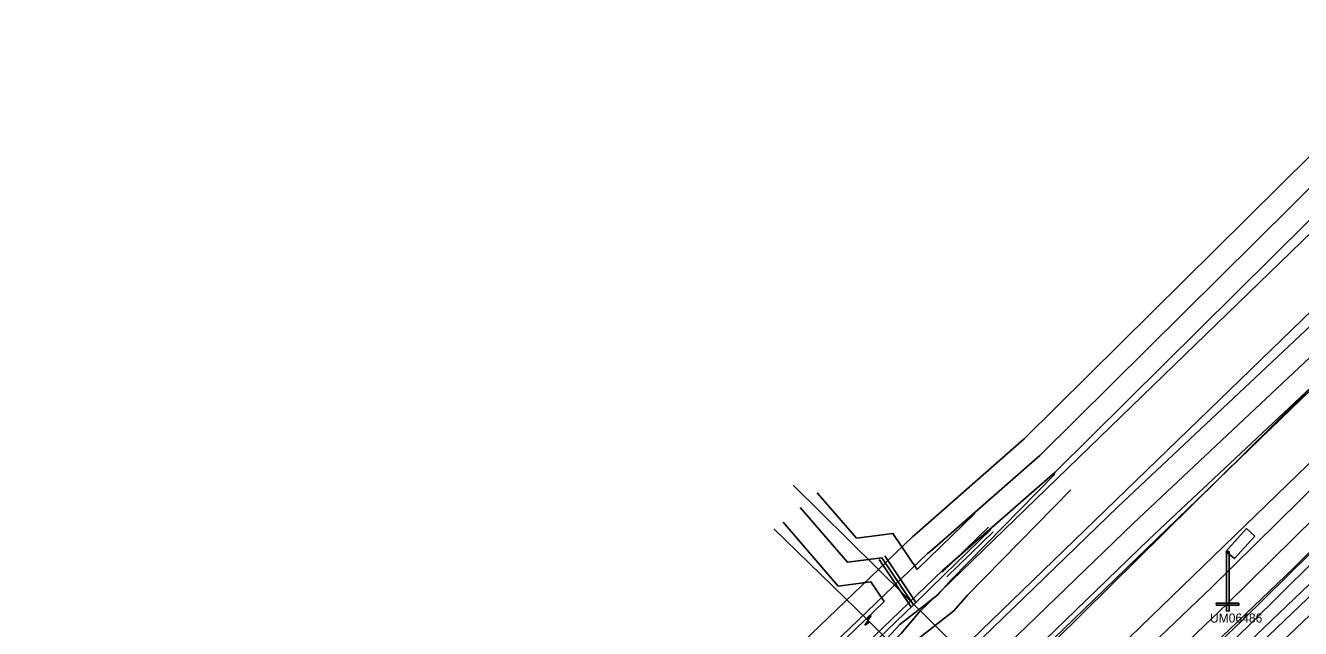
# Model space of a CAD drawing. Extents: x -762993 to -761845, y -975230 to -974501.
# Drawn here: x -762261.1 to -762204.7, y -974943.8 to -974917.1 of the extents above; entities that cross this region are included whole.
import ezdxf

# ---------------------------------------------------------------- set-up
doc = ezdxf.new("R2010")
doc.units = 0
for name, color, linetype in [('IS_CETIN_chranicka', 7, 'Continuous'), ('IS_CETIN_OP', 7, 'Continuous'), ('IS_CETIN_podzem metalika zam', 7, 'Continuous'), ('IS_CETIN_podzem optika zam', 7, 'Continuous'), ('IS_CEZ-D_el vedeni NN podzem', 7, 'Continuous'), ('IS_CEZ-D_el vedeni VN podzem', 7, 'Continuous'), ('IS_CEZ-D_el vedeni VN podzem soubeh investice', 7, 'Continuous'), ('IS_CEZ-D_OP', 7, 'Continuous'), ('IS_CEZ-T_parovod', 7, 'Continuous'), ('IS_CEZ-T_parovod OP', 7, 'Continuous'), ('IS_DPmUL_OP', 7, 'Continuous'), ('IS_DPmUL_VO lampy', 7, 'Continuous'), ('IS_DPmUL_VO lampy anotace', 7, 'Continuous'), ('IS_DPmUL_VO vedeni podzem', 7, 'Continuous'), ('IS_GASNET_plyn NTL rad', 7, 'Continuous'), ('IS_GASNET_plyn OP', 7, 'Continuous'), ('IS_SCVK_kanalizace jednotna', 7, 'Continuous'), ('IS_SCVK_vodovod pripojky', 7, 'Continuous'), ('IS_SCVK_vodovod privadec', 7, 'Continuous'), ('IS_SCVK_vodovod znaky', 7, 'Continuous'), ('IS_TPS_podzem metalika', 7, 'Continuous')]:
    doc.layers.add(name, color=color, linetype=linetype)

msp = doc.modelspace()

# ---------------------------------------------------------------- linework, layer by layer
at = {"layer": 'IS_CETIN_chranicka'}
for points in [[(-762218.494, -974939.302), (-762220.544, -974941.292)], [(-762218.286, -974939.518), (-762220.336, -974941.508)], [(-762223.334, -974940.744), (-762221.934, -974942.824)], [(-762223.086, -974940.576), (-762221.686, -974942.656)]]:
    msp.add_lwpolyline(points, dxfattribs=at)
at = {"layer": 'IS_CETIN_OP'}
for points in [[(-762221.651, -974941.186), (-762222.726, -974939.588), (-762224.334, -974939.798), (-762226.072, -974937.778)], [(-762214.836, -974937.65), (-762219.414, -974942.321), (-762220.029, -974943.012)], [(-762223.108, -974942.602), (-762223.694, -974941.732), (-762225.146, -974941.922), (-762227.588, -974939.082)], [(-762221.651, -974941.186), (-762221.138, -974940.684), (-762219.087, -974938.692)], [(-762240.314, -974959.621), (-762235.368, -974954.443), (-762229.198, -974948.525), (-762226.125, -974945.639), (-762225.209, -974944.624), (-762223.108, -974942.602)], [(-762220.029, -974943.012), (-762221.734, -974944.362), (-762224.313, -974947.13)]]:
    msp.add_lwpolyline(points, dxfattribs=at)
at = {"layer": 'IS_CETIN_podzem metalika zam'}
for points in [[(-762215.55, -974936.95), (-762220.145, -974941.638), (-762220.718, -974942.282)], [(-762221.81, -974942.74), (-762223.21, -974940.66), (-762224.74, -974940.86), (-762226.83, -974938.43)], [(-762220.718, -974942.282), (-762222.414, -974943.625), (-762225.045, -974946.448)]]:
    msp.add_lwpolyline(points, dxfattribs=at)
at = {"layer": 'IS_CETIN_podzem optika zam'}
for points in [[(-762221.81, -974942.74), (-762220.44, -974941.4), (-762218.39, -974939.41)], [(-762240.2, -974960.95), (-762234.66, -974955.15), (-762228.51, -974949.25), (-762225.41, -974946.34), (-762224.49, -974945.32), (-762221.81, -974942.74)]]:
    msp.add_lwpolyline(points, dxfattribs=at)
at = {"layer": 'IS_CEZ-D_el vedeni NN podzem'}
msp.add_lwpolyline([(-762247.847, -974984.536), (-762246.114, -974982.893), (-762246.05, -974980.697), (-762253.7, -974972.107), (-762252.057, -974970.493), (-762250.973, -974969.428), (-762239.791, -974958.41), (-762235.916, -974954.845), (-762234.541, -974953.31), (-762221.186, -974940.477), (-762220.991, -974940.306), (-762216.22, -974936.128), (-762203.456, -974923.483), (-762203.186, -974923.213), (-762202.673, -974922.708), (-762197.126, -974917.211), (-762182.367, -974902.622)], dxfattribs=at)
at = {"layer": 'IS_CEZ-D_el vedeni VN podzem'}
msp.add_lwpolyline([(-762178.94, -974917.38), (-762180.88, -974919.33), (-762183.85, -974922.18), (-762189.02, -974927.27), (-762191.6, -974929.28), (-762204.29, -974941.85), (-762215.61, -974952.68), (-762222.04, -974959.06), (-762225.71, -974962.96), (-762226.91, -974964.67), (-762236.89, -974974.42), (-762240.73, -974978.21), (-762245.09, -974982.81)], dxfattribs=at)
at = {"layer": 'IS_CEZ-D_el vedeni VN podzem soubeh investice'}
msp.add_lwpolyline([(-762246.655, -974985.018), (-762244.801, -974983.086), (-762240.444, -974978.49), (-762236.61, -974974.705), (-762226.604, -974964.93), (-762225.399, -974963.213), (-762221.753, -974959.339), (-762215.331, -974952.967), (-762204.011, -974942.137), (-762191.335, -974929.581), (-762188.756, -974927.571), (-762183.571, -974922.467), (-762180.6, -974919.615), (-762178.658, -974917.664), (-762169.2, -974908.366)], dxfattribs=at)
at = {"layer": 'IS_CEZ-D_OP'}
for points in [[(-762235.261, -974952.615), (-762221.862, -974939.74), (-762221.65, -974939.554), (-762216.902, -974935.396), (-762204.161, -974922.774), (-762203.89, -974922.503), (-762203.376, -974921.997), (-762197.829, -974916.5), (-762183.107, -974901.948), (-762182.738, -974901.004), (-762180.901, -974896.322), (-762175.443, -974882.405), (-762170.837, -974870.904), (-762171.08, -974867.387), (-762172.169, -974851.621), (-762173.361, -974831.196), (-762173.4, -974830.555), (-762173.438, -974829.89), (-762173.725, -974824.972), (-762174.311, -974821.59), (-762174.662, -974815.176), (-762174.624, -974813.433), (-762174.492, -974807.288)], [(-762252.034, -974971.872), (-762251.356, -974971.206), (-762250.272, -974970.141), (-762239.101, -974959.134), (-762235.203, -974955.548), (-762233.821, -974954.005), (-762220.51, -974941.214), (-762220.332, -974941.058), (-762215.538, -974936.86), (-762202.751, -974924.192), (-762202.482, -974923.923), (-762201.97, -974923.419), (-762196.423, -974917.922), (-762181.665, -974903.334)], [(-762179.649, -974916.675), (-762181.581, -974918.616), (-762184.547, -974921.463), (-762189.68, -974926.517), (-762192.261, -974928.528), (-762204.988, -974941.133), (-762212.335, -974948.163)], [(-762178.231, -974918.085), (-762180.179, -974920.044), (-762183.153, -974922.897), (-762188.36, -974928.023), (-762190.939, -974930.032), (-762203.592, -974942.567), (-762210.996, -974949.649)]]:
    msp.add_lwpolyline(points, dxfattribs=at)
at = {"layer": 'IS_CEZ-T_parovod'}
msp.add_line((-762219.73, -974944.77), (-762227.14, -974937.44), dxfattribs=at)
msp.add_lwpolyline([(-762252.5, -975008.59), (-762252.58, -975007.19), (-762253.19, -974987.18), (-762253.2, -974985.67), (-762257.54, -974981.54), (-762246.7, -974971.01), (-762237.24, -974961.81), (-762238.76, -974960.21), (-762237.06, -974958.42), (-762235.35, -974960.05), (-762220.52, -974945.72), (-762219.73, -974944.77), (-762200.92, -974926.55), (-762198.18, -974929.41), (-762193.38, -974924.68)], dxfattribs=at)
at = {"layer": 'IS_CEZ-T_parovod OP'}
for points in [[(-762254.996, -975008.733), (-762255.078, -975007.299), (-762255.69, -974987.226), (-762255.693, -974986.749), (-762261.147, -974981.559), (-762248.442, -974969.217), (-762240.754, -974961.74), (-762242.208, -974960.21), (-762237.148, -974954.882), (-762235.362, -974956.585), (-762222.355, -974944.017), (-762221.566, -974943.068), (-762200.854, -974923.005), (-762198.129, -974925.85), (-762195.116, -974922.881)], [(-762250.004, -975008.447), (-762250.082, -975007.081), (-762250.69, -974987.134), (-762250.707, -974984.591), (-762253.933, -974981.521), (-762244.958, -974972.803), (-762235.373, -974963.482), (-762235.338, -974963.515), (-762218.685, -974947.423), (-762217.894, -974946.472), (-762200.986, -974930.095), (-762198.231, -974932.97), (-762193.371, -974928.181)]]:
    msp.add_lwpolyline(points, dxfattribs=at)
at = {"layer": 'IS_DPmUL_OP'}
for p, q in [((-762228.861, -974961.348), (-762208.613, -974941.975)), ((-762227.465, -974962.78), (-762207.231, -974943.421))]:
    msp.add_line(p, q, dxfattribs=at)
for points in [[(-762208.624, -974941.986), (-762192.88, -974926.476)], [(-762207.22, -974943.41), (-762191.476, -974927.9)]]:
    msp.add_lwpolyline(points, dxfattribs=at)
at = {"layer": 'IS_DPmUL_VO lampy'}
for points in [[(-762207.062, -974939.368), (-762206.692, -974939.698), (-762207.592, -974940.698), (-762207.972, -974940.378)], [(-762207.952, -974940.378), (-762207.832, -974940.388), (-762207.832, -974943.028), (-762207.952, -974943.018)], [(-762208.402, -974942.678), (-762207.402, -974942.678), (-762207.402, -974942.768), (-762208.392, -974942.768)]]:
    msp.add_lwpolyline(points, close=True, dxfattribs=at)
at = {"layer": 'IS_DPmUL_VO vedeni podzem'}
for points in [[(-762207.922, -974942.698), (-762192.178, -974927.188)], [(-762228.163, -974962.064), (-762207.922, -974942.698)]]:
    msp.add_lwpolyline(points, dxfattribs=at)
at = {"layer": 'IS_GASNET_plyn NTL rad'}
msp.add_lwpolyline([(-762254.38, -974980.34), (-762254.3, -974980.18), (-762254.49, -974979.97), (-762249.33, -974975.11), (-762246.79, -974972.7), (-762240.45, -974966.56), (-762232.17, -974958.5), (-762223.94, -974950.53), (-762218.08, -974944.94), (-762212.07, -974939.13), (-762200.83, -974928.57), (-762199.24, -974927.03), (-762198.4, -974925.79), (-762191.542, -974918.748)], dxfattribs=at)
at = {"layer": 'IS_GASNET_plyn OP'}
for points in [[(-762218.773, -974944.219), (-762212.76, -974938.406), (-762201.52, -974927.846)], [(-762200.14, -974929.294), (-762211.38, -974939.854), (-762217.387, -974945.661)]]:
    msp.add_lwpolyline(points, dxfattribs=at)
at = {"layer": 'IS_SCVK_kanalizace jednotna'}
msp.add_lwpolyline([(-762237.305, -974965.834), (-762203.442, -974932.379)], dxfattribs=at)
at = {"layer": 'IS_SCVK_vodovod pripojky'}
for points in [[(-762223.825, -974943.439), (-762227.995, -974939.385)], [(-762217.757, -974949.459), (-762223.825, -974943.439)]]:
    msp.add_lwpolyline(points, dxfattribs=at)
at = {"layer": 'IS_SCVK_vodovod privadec'}
msp.add_lwpolyline([(-762201.113, -974933.408), (-762202.03, -974934.3), (-762216.385, -974948.217)], dxfattribs=at)
at = {"layer": 'IS_SCVK_vodovod znaky'}
for points in [[(-762223.686, -974943.226), (-762223.964, -974943.652)], [(-762223.964, -974943.652), (-762223.753, -974943.509)], [(-762223.686, -974943.226), (-762223.897, -974943.369)]]:
    msp.add_lwpolyline(points, dxfattribs=at)
at = {"layer": 'IS_TPS_podzem metalika'}
msp.add_lwpolyline([(-762172.29, -974910.28), (-762185.23, -974922.87), (-762190.46, -974927.24), (-762198, -974934.74), (-762201.39, -974938.15), (-762206.9, -974943.61), (-762214.43, -974950.91), (-762220.21, -974956.46), (-762222.55, -974958.76), (-762223.79, -974960.27), (-762224.33, -974962.55), (-762233.162, -974970.759), (-762240.486, -974977.956), (-762246.238, -974984.004)], dxfattribs=at)

# ---------------------------------------------------------------- texts
at = {"layer": 'IS_DPmUL_VO lampy anotace'}
msp.add_text('UM06486', height=0.4, dxfattribs=at).set_placement((-762208.678, -974943.531))

doc.saveas('drawing.dxf')
